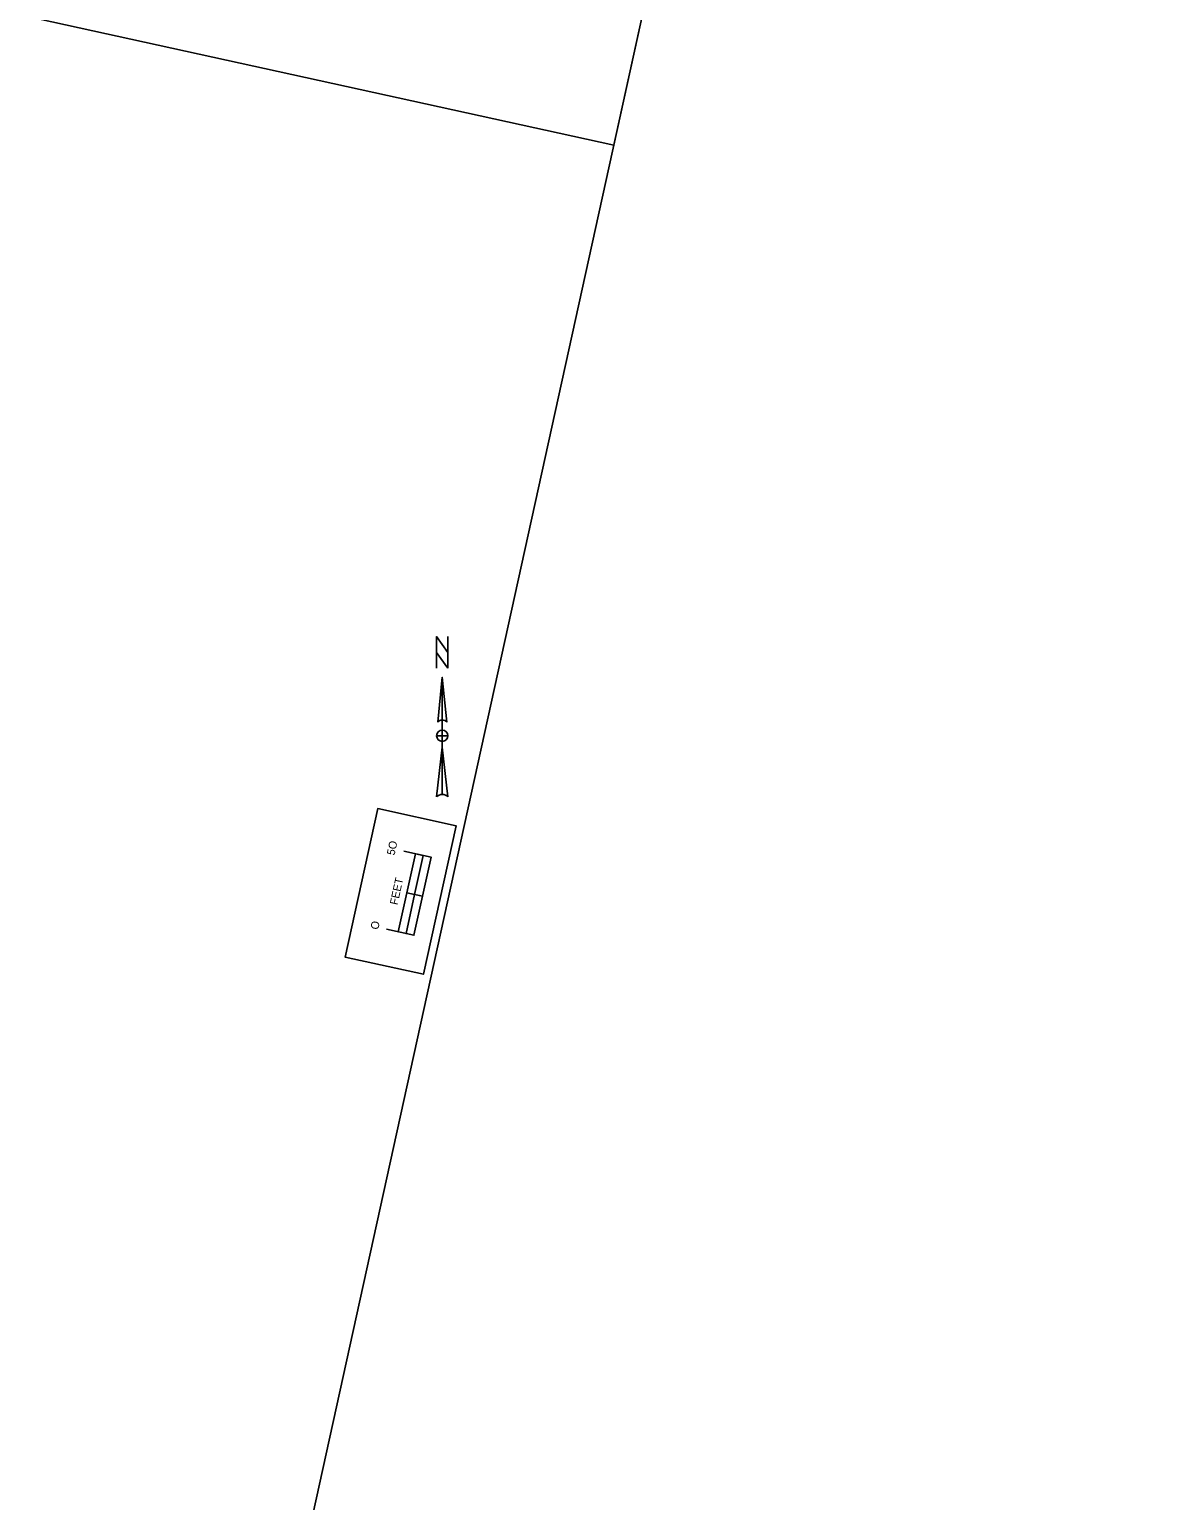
# Model space of a CAD drawing. Extents: x 14104283 to 14121738, y 8635219 to 8671666.
# Drawn here: x 14108112 to 14108813, y 8638817 to 8639736 of the extents above; entities that cross this region are included whole.
import ezdxf

# ---------------------------------------------------------------- set-up
doc = ezdxf.new("R2010")
doc.units = 0
for name, color, linetype in [('dsnCellsNorthArrow', 7, 'Continuous'), ('dsnCellsScaleBlock', 7, 'Continuous'), ('dsnNonPlotable', 7, 'Continuous')]:
    doc.layers.add(name, color=color, linetype=linetype)

msp = doc.modelspace()

# ---------------------------------------------------------------- linework, layer by layer
at = {"layer": 'dsnCellsNorthArrow'}
for p, q in [((14108369.85, 8639331.32), (14108372.67, 8639303.15)), ((14108369.85, 8639331.32), (14108369.85, 8639258.08)), ((14108367.03, 8639303.15), (14108367.03, 8639303.15)), ((14108367.14, 8639303.42), (14108367.67, 8639304)), ((14108369.85, 8639291.18), (14108369.85, 8639291.18)), ((14108366.33, 8639256.67), (14108369.85, 8639287.66))]:
    msp.add_line(p, q, dxfattribs=at)
msp.add_lwpolyline([(14108373.37, 8639336.96), (14108366.33, 8639346.82), (14108366.33, 8639356.68), (14108373.37, 8639346.82)], close=True, dxfattribs=at)
for points in [[(14108366.33, 8639336.96), (14108366.33, 8639356.68), (14108373.37, 8639346.82), (14108373.37, 8639356.68)], [(14108367.03, 8639303.15), (14108369.85, 8639331.32), (14108369.85, 8639304.56)], [(14108373.37, 8639294.7), (14108369.85, 8639294.7), (14108369.85, 8639298.22)], [(14108369.85, 8639291.18), (14108369.85, 8639294.7), (14108366.33, 8639294.7)], [(14108369.85, 8639258.08), (14108369.85, 8639287.66), (14108373.37, 8639256.67)]]:
    msp.add_lwpolyline(points, dxfattribs=at)
for centre, radius, start, end in [((14108369.85, 8639294.7), 3.52, 90, 180), ((14108369.85, 8639301.04), 3.52, 90.02039, 143.12574), ((14108369.85, 8639301.04), 3.52, 36.84806, 90.02184), ((14108369.85, 8639294.7), 3.52, 0, 90), ((14108369.85, 8639294.7), 3.52, 180, 270), ((14108369.85, 8639294.7), 3.52, 270, 360), ((14108369.85, 8639252.98), 5.1, 89.98939, 133.61895), ((14108369.85, 8639252.97), 5.11, 46.40206, 90.00064)]:
    msp.add_arc(centre, radius, start, end, dxfattribs=at)
at = {"layer": 'dsnCellsScaleBlock'}
msp.add_line((14108357.48, 8639194.5), (14108347.71, 8639196.65), dxfattribs=at)
msp.add_line((14108357.48, 8639194.5), (14108347.71, 8639196.65), dxfattribs=at)
for points in [[(14108358.03, 8639145.75), (14108309.19, 8639156.48), (14108329.58, 8639249.26), (14108378.42, 8639238.53)], [(14108309.19, 8639156.48), (14108329.58, 8639249.26), (14108378.42, 8639238.53), (14108358.03, 8639145.75)], [(14108358.03, 8639145.75), (14108309.19, 8639156.48), (14108329.58, 8639249.26), (14108378.42, 8639238.53)], [(14108352.56, 8639195.58), (14108357.93, 8639220), (14108353.08, 8639221.07), (14108347.71, 8639196.65)], [(14108352.11, 8639170.08), (14108357.48, 8639194.5), (14108352.56, 8639195.58), (14108347.2, 8639171.17)]]:
    msp.add_lwpolyline(points, close=True, dxfattribs=at)
for points in [[(14108335.02, 8639173.84), (14108352.11, 8639170.08), (14108362.84, 8639218.92), (14108345.75, 8639222.68)], [(14108342.35, 8639172.23), (14108353.08, 8639221.07)]]:
    msp.add_lwpolyline(points, dxfattribs=at)
at = {"layer": 'dsnNonPlotable'}
for points in [[(14107490.45, 8639880.3), (14107826.84, 8641411.28), (14108813.31, 8641194.53), (14108476.92, 8639663.55)], [(14107218.44, 8638642.33), (14107554.83, 8640173.31), (14108541.3, 8639956.56), (14108204.91, 8638425.58)]]:
    msp.add_lwpolyline(points, close=True, dxfattribs=at)

# ---------------------------------------------------------------- texts
at = {"layer": 'dsnCellsScaleBlock'}
for s, p in [('5O', (14108339.99, 8639219.77)), ('FEET', (14108341.88, 8639188.74)), ('O', (14108329.79, 8639173.32))]:
    msp.add_text(s, height=5, rotation=77.60784, dxfattribs=at).set_placement(p)

doc.saveas('drawing.dxf')
